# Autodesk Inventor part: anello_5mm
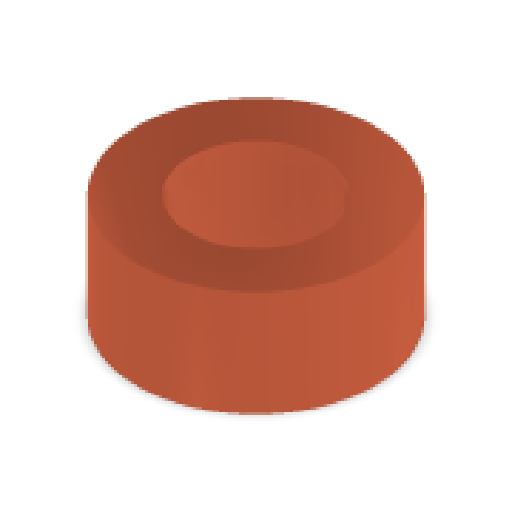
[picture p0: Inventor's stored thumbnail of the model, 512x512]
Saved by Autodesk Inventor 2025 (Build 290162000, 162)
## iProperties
Created: 2025-04
Part Number: anello_5mm
Material: Generico
Document SubType Name: Modeling
Designer: R5800u
Density: 1 g/cm^3
Appearance: Metallo 1400F caldo
Author: R5800u
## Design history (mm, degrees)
sketch "Schizzo1"
  geometry: C1 r 2.5 at (0, 0); C2 r 4.5 at (0, 0); 1 further point
  constraints: 2 centre point, 2 coincident
  dimensions: "d0" = 5 diameter of C1; "d1" = 9 diameter of C2
extrude "Estrusione1" new body sketch "Schizzo1" distance "d2" = 4; taper "d3" = 0 deg
node "Solido1"
